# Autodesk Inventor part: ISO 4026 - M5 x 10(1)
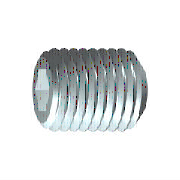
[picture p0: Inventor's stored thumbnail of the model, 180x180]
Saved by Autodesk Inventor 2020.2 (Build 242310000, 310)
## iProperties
Created: 2019-01
Part Number: ISO 4026 - M5 x 10(1)
Material: Edelstahl, 440C
Description: Innensechskant-Gewindestifte mit Kegelstumpf
Document SubType Name: Modeling
Standard: ISO 4026
Designer: lutzd
Standard Revision: Third edition 2003-12-01
Standards Organization: ISO
Language: de-DE
Size Designation: M5 x 10
Categories: <MemberInstance><Categories><Category DisplayName="Verbindungselemente" InternalName="e4da775c-781d-43d5-af7c-5136215cf5a6" Mnemonic="FSTN"><Category DisplayNam
Mass: 1.35476 g
Surface Area: 2.14145 cm^2
Volume: 0.174808 cm^3
Density: 7.75 g/cm^3
Appearance: Semi-Polished(3)
IsCustomPart: 0
Author: lutzd
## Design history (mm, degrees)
sketch "Skizze1"
  geometry: L1 (0, 0)-(6.167, 0); L2 (10, 1.443)-(10, 2.5); L3 (10, 2.5)-(0, 2.5); L4 (10, 1.443)-(7, 1.443); L5 (7, 1.443)-(6.167, 0); L6 (0, -0.5)-(0, 3) reference; L7 (0, 2.5)-(0, 0)
  constraints: 13 end point, 3 parallel, 1 collinear, 1 perpendicular, 1 point on line
  dimensions: "d0" = 3 distance of L2.start L4.end (= INTI); "d1" = 60 deg angle of L5 L1; "d2" = 5 diameter of L3 L1 (= NND); "d3" = 2.88675 diameter of L4 L1 (= 1.1547 x SW); "d5" = 10 distance from line of L2 L3.end (= NLG)
revolve "Körper" sketch "Skizze1" stored, may be unused: angle "d6" = 90 deg
sketch "Skizze2"
  geometry: L1 (-0.722, 1.25)-(0.722, 1.25); L2 (0.722, 1.25)-(1.443, 0); L3 (1.443, 0)-(0.722, -1.25); L4 (0.722, -1.25)-(-0.722, -1.25); L5 (-0.722, -1.25)-(-1.443, 0); L6 (-1.443, 0)-(-0.722, 1.25); A1 r 1.443 centre (0, 0) between (-0.722, 1.25) and (0.722, 1.25) reference; 2 further points
  constraints: 12 end point, 2 point on circle, 1 coincident, 1 horizontal, 11 other
extrude "Loch" join sketch "Skizze2" taper "d9" = 0 deg; stored distance "d21" = 10
workaxis "Work Axis1"
workplane "Work Plane1"
body "Solid1"
chamfer "Fase1" distance "d7" = 0.49076 (= -0.5 x GD1 + 0.5 x NND); stored, may be unused: angle "d8" = 45 deg (= FAWI), second distance "d29" = 0.49076 (= -0.5 x GD1 + 0.5 x NND)
feature "Gewinde" dims "d11" = 10 (= NLG), "d12" = 0
chamfer "Fase2" distance "d13" = 0.49076 (= -0.5 x GD1 + 0.5 x NND); stored, may be unused: angle "d14" = 45 deg (= FAWI), second distance "d30" = 0.49076 (= -0.5 x GD1 + 0.5 x NND)
other parameters: "NND" = 5 [user parameter; used in 5 equation terms], "NLG" = 10 [user parameter; used in 2 equation terms], "INTI" = 3 [user parameter; used in 1 equation term], "FAWI" = 45 deg [user parameter; used in 2 equation terms], "SW" = 2.5 [user parameter; used in 2 equation terms], "GD1" = 4.01848 (= THREADDIA - 1.2269 x PTC) [user parameter; used in 4 equation terms], "d4" = 0, "FAWI1" = 45 deg [user parameter], "d15" = 0, "d31" = 0, "GUL" = 0.49076 (= 0.61345 x PTC) [user parameter], "SPD" = 3.5 [user parameter], "SEWI" = 90 deg [user parameter], "TOA" = 30 deg [user parameter], "THREADDIA" = 5 [user parameter; used in 1 equation term], "TPU" = 12.5 (computed from PTC) [user parameter], "PTC" = 0.8 [user parameter; used in 4 equation terms], "GAL" = 0.49076 (= 0.61345 x PTC) [user parameter], "E0" = 2.8875 (= 1.155 x SW) [user parameter]
